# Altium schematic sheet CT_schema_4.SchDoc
size 461 x 327 mm
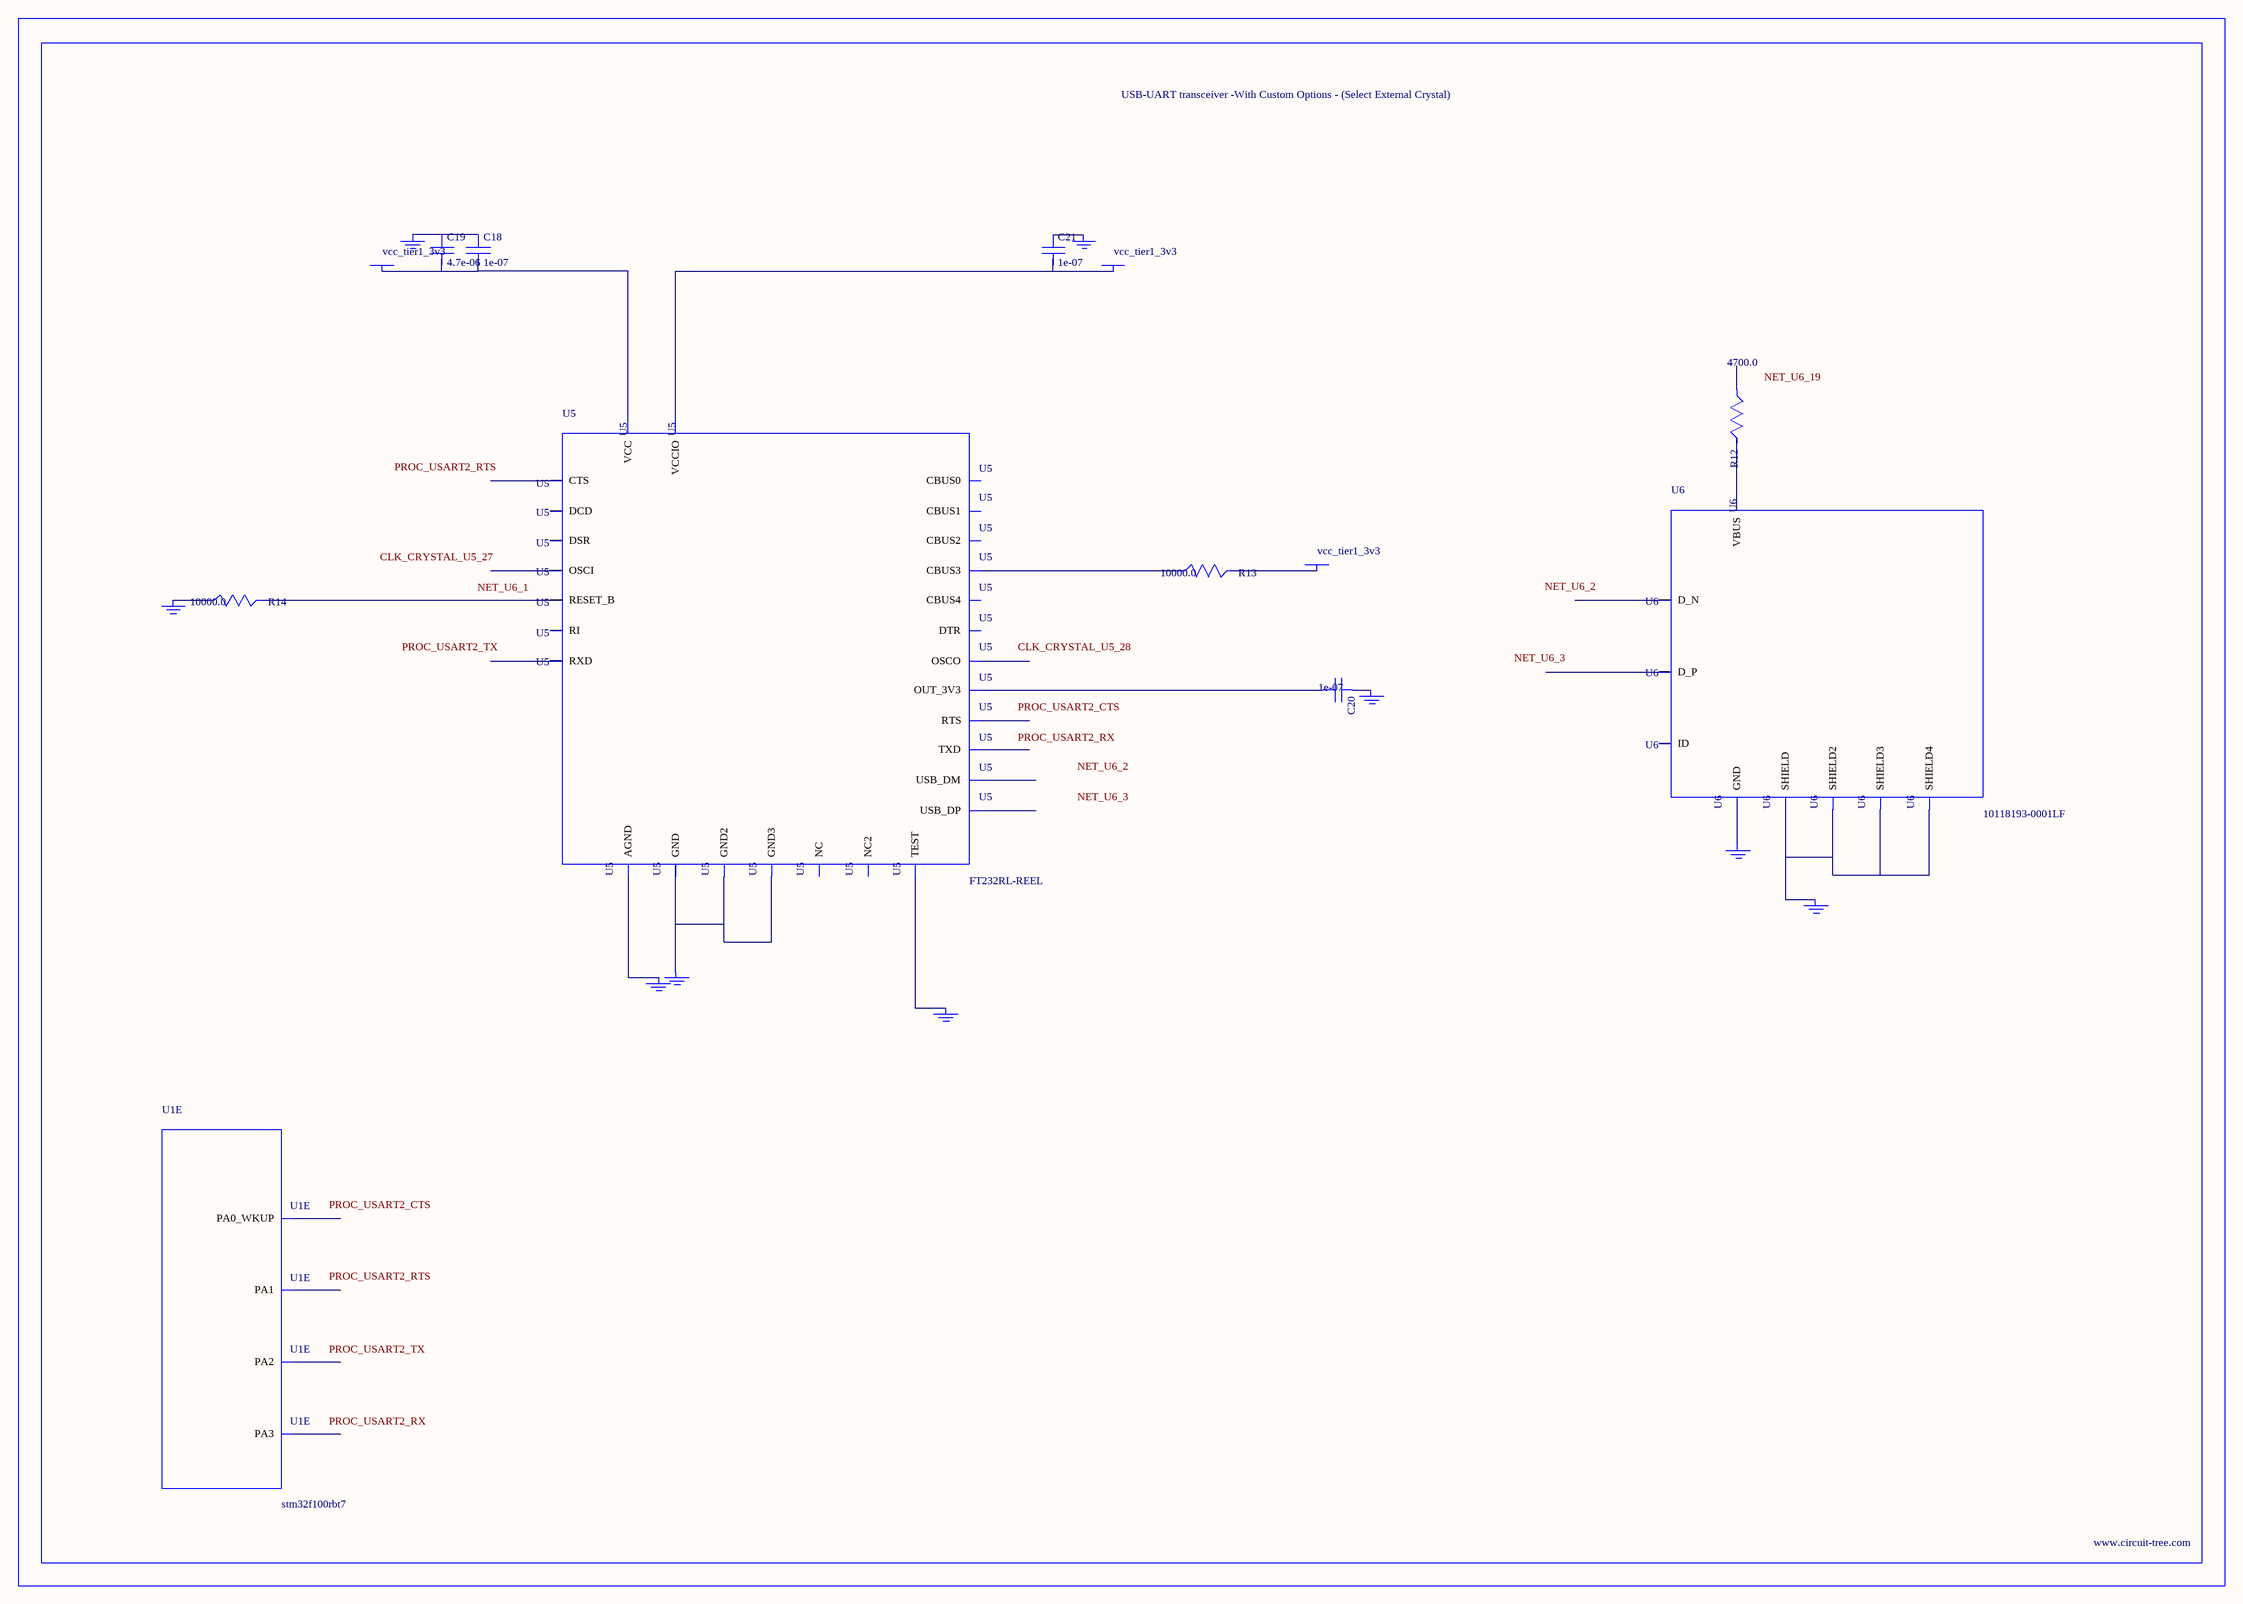
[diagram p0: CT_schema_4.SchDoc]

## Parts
BORDER3  (no value)
C18  1e-07  [C0402]
C19  4.7e-06  [C0805]
C20  1e-07  [C0402]
C21  1e-07  [C0402]
GND_INSTANCE_3_0  (no value)
GND_INSTANCE_3_1  (no value)
GND_INSTANCE_3_2  (no value)
GND_INSTANCE_3_3  (no value)
GND_INSTANCE_3_4  (no value)
GND_INSTANCE_3_5  (no value)
GND_INSTANCE_3_6  (no value)
GND_INSTANCE_3_7  (no value)
GND_INSTANCE_3_8  (no value)
POWER_INSTANCE_3_0  vcc_tier1_3v3
POWER_INSTANCE_3_1  vcc_tier1_3v3
POWER_INSTANCE_3_2  vcc_tier1_3v3
R12  4700.0  [R0603]
R13  10000.0  [R0603]
R14  10000.0  [R0603]
U1  stm32f100rbt7  [LQFP64]  (part E of 6)
U5  FT232RL-REEL  [SSOP-28]
U6  10118193-0001LF  [FCI_10118193-0001LF]

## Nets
NetC18_1: C18.1 C19.1 GND_INSTANCE_3_3.0(GND)
NetC18_2: C18.2 C19.2 POWER_INSTANCE_3_2.0(PWR) U5.20(VCC)
NetC20_1: C20.1 GND_INSTANCE_3_1.0(GND)
NetC20_2: C20.2 U5.17(OUT_3V3)
NetC21_1: C21.1 GND_INSTANCE_3_0.0(GND)
NetC21_2: C21.2 POWER_INSTANCE_3_0.0(PWR) U5.4(VCCIO)
NetGND_INSTANCE_3_2_0: GND_INSTANCE_3_2.0(GND) R14.1
NetGND_INSTANCE_3_4_0: GND_INSTANCE_3_4.0(GND) U5.25(AGND)
NetGND_INSTANCE_3_5_0: GND_INSTANCE_3_5.0(GND) U5.26(TEST)
NetGND_INSTANCE_3_6_0: GND_INSTANCE_3_6.0(GND) U5.7(GND) U5.18(GND2) U5.21(GND3)
NetGND_INSTANCE_3_7_0: GND_INSTANCE_3_7.0(GND) U6.6(SHIELD) U6.7(SHIELD2) U6.8(SHIELD3) U6.9(SHIELD4)
NetGND_INSTANCE_3_8_0: GND_INSTANCE_3_8.0(GND) U6.5(GND)
NetPOWER_INSTANCE_3_1_0: POWER_INSTANCE_3_1.0(PWR) R13.2
NetR12_2: R12.2 U6.1(VBUS)
NetR13_1: R13.1 U5.14(CBUS3)
NetR14_2: R14.2 U5.19(RESET_B)

Not connected (* = marked no-connect by the designer): R12 1; U1 14(PA0_WKUP) 15(PA1) 16(PA2) 17(PA3); U5 1(TXD) 2(DTR) 3(RTS) 5(RXD) 6(RI) 8(NC) 9(DSR) 10(DCD) 11(CTS) 12(CBUS4) 13(CBUS2) 15(USB_DP) 16(USB_DM) 22(CBUS1) 23(CBUS0) 24(NC2) 27(OSCI) 28(OSCO); U6 2(D_N) 3(D_P) 4(ID)

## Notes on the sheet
- Labels drawn without touching a wire or pin: CLK_CRYSTAL_U5_27, CLK_CRYSTAL_U5_28, NET_U6_1, NET_U6_2, NET_U6_3, NET_U6_19, PROC_USART2_CTS, PROC_USART2_RTS, PROC_USART2_RX, PROC_USART2_TX

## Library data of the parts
BORDER3 = BORDER_PAGE3
C18 C20 C21 = C0402C104K3RACTU
C19 = C0805C475K4RACTU
GND_INSTANCE_3_0-GND_INSTANCE_3_8 = GND
POWER_INSTANCE_3_0-POWER_INSTANCE_3_2 = PWR
R12 = RC0603JR-074K7L
R13 R14 = RC0603JR-0710KL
